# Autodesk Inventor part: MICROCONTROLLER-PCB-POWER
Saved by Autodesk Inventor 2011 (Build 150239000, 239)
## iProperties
Created: 2007-09
Part Number: MICROCONTROLLER-PCB-POWER
Document SubType Name: Modeling
Density: 1 g/cm^3
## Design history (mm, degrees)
feature "Base1"
body "Solid1"
